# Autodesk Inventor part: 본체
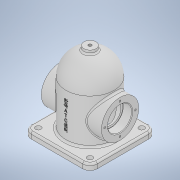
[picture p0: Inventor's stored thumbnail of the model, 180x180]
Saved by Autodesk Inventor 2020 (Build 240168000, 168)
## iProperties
Created: 2021-07
Part Number: 본체
Material: 일반
Document SubType Name: Modeling
Designer: Owner
Density: 1 g/cm^3
Appearance: 기본값
Author: Owner
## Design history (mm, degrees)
sketch "스케치1"
  geometry: C1 r 40 at (0, 0); 1 further point
  constraints: 1 centre point, 1 coincident
  dimensions: "d0" = 80 diameter of C1
extrude "돌출1" new body sketch "스케치1" distance "d1" = 124; taper "d2" = 0 deg
fillet "모깎기1" dims "d3" = 40
feature "쉘1" dims "d4" = 8
sketch "스케치2"
  geometry: L1 (55, 55)-(-55, 55); L2 (-55, 55)-(-55, -55); L3 (-55, -55)-(55, -55); L4 (55, -55)-(55, 55); L5 (55, 55)-(-55, -55); L6 (-55, 55)-(55, -55); C1 r 32 at (0, 0) reference; C2 r 40 at (0, 0) reference; 1 further point
  constraints: 12 end point, 2 midpoint, 2 parallel, 1 horizontal, 1 perpendicular
  dimensions: "d5" = 110 distance of L3.end L2.end; "d6" = 110 distance of L2.end L1.end
extrude "돌출2" join sketch "스케치2" distance "d7" = 10; taper "d8" = 0 deg
node "작업 평면1"
sketch "스케치3"
  geometry: L1 (-55, 0)-(55, 0) reference; C1 r 31 at (0, 48); 2 further points
  constraints: 1 centre point, 1 midpoint, 1 vertical alignment
  dimensions: "d10" = 62 diameter of C1; "d11" = 48 distance from line of L1 C1.centre
extrude "돌출3" join sketch "스케치3" stored distance "d12" = 10; taper "d13" = 0 deg
sketch "스케치4"
  geometry: C1 r 31 at (0, 0) reference; 2 further points
  constraints: 1 coincident
hole "구멍1" sketch "스케치4" at (0, 0) diameter "d14" = 33; stored, may be unused: countersink angle "d18" = 90 deg, drill point angle "d20" = 118 deg; dims "d15" = 6, "d16" = 40, "d17" = 15, "d19" = 8
sketch "스케치5"
  geometry: C1 r 20 at (0, 0) reference; 2 further points
  constraints: 1 vertical alignment
  dimensions: "d21" = 25.5 distance of C1.centre point (0, 25.5)
hole "구멍2" sketch "스케치5" at (0, 25.5) diameter "d22" = 3.242; stored, may be unused: countersink angle "d26" = 90 deg, drill point angle "d28" = 118 deg; dims "d23" = 8, "d24" = 40, "d25" = 15, "d27" = 10
node "작업 평면2"
sketch "스케치6"
  geometry: C1 r 10 at (0, 0); 1 further point
  constraints: 1 centre point, 1 coincident
  dimensions: "d33" = 20 diameter of C1
extrude "돌출4" join sketch "스케치6" stored distance "d34" = 124; taper "d35" = 0 deg
sketch "스케치8"
  geometry: C1 r 10 at (0, 0) reference; 2 further points
  constraints: 1 coincident
hole "구멍3" sketch "스케치8" at (0, 0) diameter "d36" = 5.1881; stored, may be unused: countersink angle "d40" = 90 deg, drill point angle "d42" = 118 deg; dims "d37" = 30, "d38" = 40, "d39" = 15, "d41" = 16
fillet "모깎기2" dims "d43" = 12
fillet "모깎기3" dims "d44" = 3
sketch "스케치9"
  geometry: A1 r 12 centre (43, -43) between (43, -55) and (55, -43) reference; 2 further points
  constraints: 1 coincident
hole "구멍4" sketch "스케치9" at (43, -43) diameter "d45" = 9; stored, may be unused: countersink angle "d49" = 90 deg, drill point angle "d51" = 118 deg; dims "d46" = 30, "d47" = 40, "d48" = 15, "d50" = 16
fillet "모깎기4" dims "d55" = 0.3
node "작업 평면3"
sketch "스케치10"
  geometry: L1 (0, 43)-(0, -43) reference; 3 further points
  constraints: 1 horizontal alignment, 1 midpoint, 1 other
  dimensions: "d56" = 48 distance from line of L1 point (48, 0)
feature "엠보싱1" sketch "스케치10" dims "d57" = 0.5, "d58" = 0
chamfer "모따기1" distance "d59" = 1; stored, may be unused: second distance "d60" = 2, angle "d61" = 45 deg
node "솔리드1"
pattern_circular "원형 패턴1" dims angle "d30" = 360 deg
mirror "미러1"
pattern_circular "원형 패턴2" dims angle "d53" = 360 deg
node "절단 모서리 투영1"
feature "A9D066F2-1C7D-4E18-AEED-F7BC21143FA4" dims "d36" = 5.1881, "d37" = 30, "d38" = 40, "d39" = 15, "d40" = 90 deg, "d41" = 16, "d42" = 118 deg
other parameters: "d32" = 129
